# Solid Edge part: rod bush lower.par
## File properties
Author: Robert a Rhodes jr
Template: Normal.par
Last saved by: Cadcim
Revision: 5
Application: Solid Edge
Accuracy: 0.99
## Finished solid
Body 1: solid body, 4 faces, 4 edges, 0 vertices.
  Faces by surface: cylinder 2, plane 2
  Edges by curve: circle 4
Bounding box of the edges (mm): 15.000 x 15.000 x 24.000, from (-7.5, -7.5, -24) to (7.5, 7.5, 0).
Cylindrical faces by radius (mm): R6 x1, R7.5 x1
Planar faces by outward normal: +z 1, -z 1
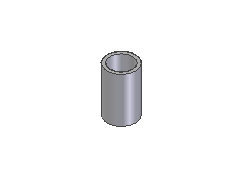
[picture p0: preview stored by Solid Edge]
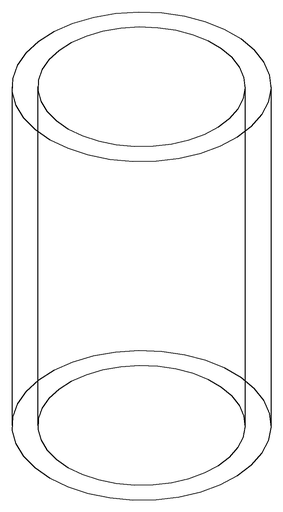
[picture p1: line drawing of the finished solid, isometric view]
